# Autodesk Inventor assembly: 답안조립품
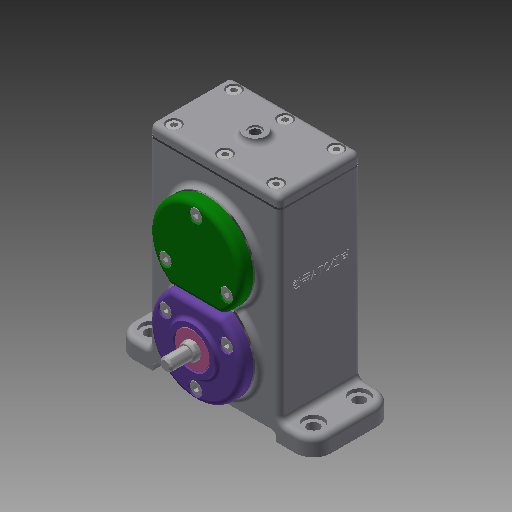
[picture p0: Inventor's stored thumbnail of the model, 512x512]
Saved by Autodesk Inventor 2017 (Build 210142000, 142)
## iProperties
Part Number: 답안조립품
Material: 일반
Document SubType Name: Assembly
Designer: mrc
Author: mrc
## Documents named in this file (24)
- C:\Users\mrc\Desktop\600506V1015\답안조립품.iam
- C:\Users\mrc\Desktop\600506V1015\본체.ipt
- C:\Users\mrc\Desktop\600506V1015\개스킷 A.ipt
- C:\Users\mrc\Desktop\600506V1015\개스킷 B.ipt
- C:\Users\mrc\Desktop\600506V1015\개스킷 C.ipt
- C:\Users\mrc\Desktop\600506V1015\베어링 6001.ipt
- 베어링 6001.ipt
- C:\Users\mrc\Desktop\600506V1015\베어링 6002.ipt
- 베어링 6002.ipt
- C:\Users\mrc\Desktop\600506V1015\볼트 M4.ipt
- C:\Users\mrc\Desktop\600506V1015\스퍼기어 A.ipt
- C:\Users\mrc\Desktop\600506V1015\스퍼기어 B.ipt
- C:\Users\mrc\Desktop\600506V1015\오일 실 10 20 7.ipt
- C:\Users\mrc\Desktop\600506V1015\오일 실 12 22 7.ipt
- C:\Users\mrc\Desktop\600506V1015\축 A.ipt
- C:\Users\mrc\Desktop\600506V1015\축 B.ipt
- C:\Users\mrc\Desktop\600506V1015\칼라.ipt
- C:\Users\mrc\Desktop\600506V1015\커버 A.ipt
- C:\Users\mrc\Desktop\600506V1015\커버 B.ipt
- C:\Users\mrc\Desktop\600506V1015\커버 C.ipt
- C:\Users\mrc\Desktop\600506V1015\커버 D.ipt
- C:\Users\mrc\Desktop\600506V1015\커버 E.ipt
- C:\Users\mrc\Desktop\600506V1015\키 4 x 4 x 12.ipt
- C:\Users\mrc\Desktop\600506V1015\키 5 x 5 x 12.ipt
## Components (5 placed, 3 different names)
1. 개스킷 A:1
2. 개스킷 B:1
3. 개스킷 C:1
4. 개스킷 B:2
5. 개스킷 B:3
